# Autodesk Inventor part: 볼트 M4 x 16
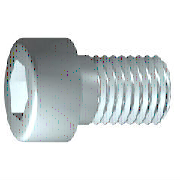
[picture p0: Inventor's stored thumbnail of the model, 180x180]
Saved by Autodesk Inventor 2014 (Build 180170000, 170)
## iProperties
Created: 2012-02
Part Number: 볼트 M4 x 16
Material: 스테인리스강
Description: 6각 소켓 머리 캡 나사
Document SubType Name: Modeling
Standard: ISO 4762
Designer: mduedu
Standard Revision: Fourth edition 2004-03-01
Standards Organization: ISO
Language: ko-KR
Size Designation: M4 x 16
Categories: <MemberInstance><Categories><Category DisplayName="조임쇠" InternalName="e4da775c-781d-43d5-af7c-5136215cf5a6" Mnemonic="FSTN"><Category DisplayName="볼트" InternalN
Density: 8.08 g/cm^3
Mass: 2.70334 g
Surface Area: 3.81118 cm^2
Volume: 0.334572 cm^3
Appearance: 반광택
IsCustomPart: 0
Author: mduedu
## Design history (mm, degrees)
sketch "스케치1"
  geometry: L1 (-1, 0)-(16, 0); L2 (16, 0)-(16, 2); L3 (16, 2)-(1.75, 2); L4 (1.75, 2)-(1.32, 2); L5 (1.32, 2)-(0, 2); L6 (0, 2)-(0, 3.5); L7 (0, 3.5)-(-4, 3.5); L8 (-4, 3.5)-(-4, 1.732); L9 (-4, 1.732)-(-2, 1.732); L10 (-2, 1.732)-(-1, 0); L11 (-8, 0)-(20, 0) reference; L12 (0, -0.7)-(0, 4.2) reference; L13 (1.75, 2)-(0, 2)
  constraints: 22 end point, 6 parallel, 2 collinear, 2 perpendicular, 1 horizontal, 1 point on line
  dimensions: "d1" = 14.25 distance from line of L3.end L2 (= GEL); "d2" = 0.42952 distance of L4.end L3.end (computed from GAL); "d3" = 4 distance between parallel lines of L8 L6 (= KOH); "d4" = 2 distance of L8.end L9.end (= INTI); "d5" = 60 deg angle of L10 L1; "d6" = 4 diameter of L3 L1 (= GD); "d7" = 4 diameter of L5 L1 (= BDM); "d8" = 3.4641 diameter of L9 L1 (= 1.1547 x SW); "d9" = 7 diameter of L7 L1 (= KOD); "d26" = 16 distance between parallel lines of L12 L2 (= NLG)
revolve "본체" sketch "스케치1" stored, may be unused: angle "d10" = 90 deg
sketch "스케치2"
  geometry: L1 (0, -4.9)-(0, 4.9) reference; L2 (-4.9, 0)-(4.9, 0) reference; L3 (1.732, 0)-(0.866, -1.5); L4 (0.866, -1.5)-(-0.866, -1.5); L5 (-0.866, -1.5)-(-1.732, 0); L6 (-1.732, 0)-(-0.866, 1.5); L7 (-0.866, 1.5)-(0.866, 1.5); L8 (0.866, 1.5)-(1.732, 0); 2 further points
  constraints: 12 end point, 1 coincident, 1 horizontal alignment, 1 point on line, 12 other
extrude "슬롯" join sketch "스케치2" stored distance "d11" = 10; taper "d12" = 0 deg
workplane "Work Plane1"
fillet "Fillet2" dims "d30" = 0.1 (= R)
body "Solid1"
fillet "모깎기1" dims "d17" = 0.4 (= RR)
feature "스레드" dims "d13" = 14.25 (= GEL), "d14" = 0
chamfer "모따기1" distance "d15" = 0.42941 (= -0.5 x SPD + 0.5 x GD); stored, may be unused: second distance "d16" = 0.42941 (= GUL), angle "d27" = 45 deg
other parameters: "GD" = 4 [user parameter; used in 2 equation terms], "NLG" = 16 [user parameter; used in 1 equation term], "GEL" = 14.25 [user parameter; used in 2 equation terms], "KOD" = 7 [user parameter; used in 1 equation term], "KOH" = 4 [user parameter; used in 1 equation term], "INTI" = 2 [user parameter; used in 1 equation term], "GAL" = 0.42941 (= 0.61345 x PTC) [user parameter; used in 1 equation term], "GUL" = 0.42941 (= 0.61345 x PTC) [user parameter; used in 1 equation term], "BDM" = 4 (= NND) [user parameter; used in 1 equation term], "SW" = 3 [user parameter; used in 2 equation terms], "RR" = 0.4 [user parameter; used in 1 equation term], "SPD" = 3.14117 (= NND - 1.2269 x PTC) [user parameter; used in 1 equation term], "d19" = 0, "d28" = 0, "d29" = 0, "R" = 0.1 [user parameter; used in 1 equation term], "TOA" = 30 deg [user parameter], "GD1" = 3.14117 (= THREADDIA - 1.2269 x PTC) [user parameter], "THREADDIA" = 4 [user parameter; used in 1 equation term], "FAWI" = 45 deg [user parameter], "TPU" = 14.28571 (computed from PTC) [user parameter], "PTC" = 0.7 [user parameter; used in 5 equation terms], "NND" = 4 [user parameter; used in 2 equation terms], "E0" = 3.465 (= 1.155 x SW) [user parameter]
